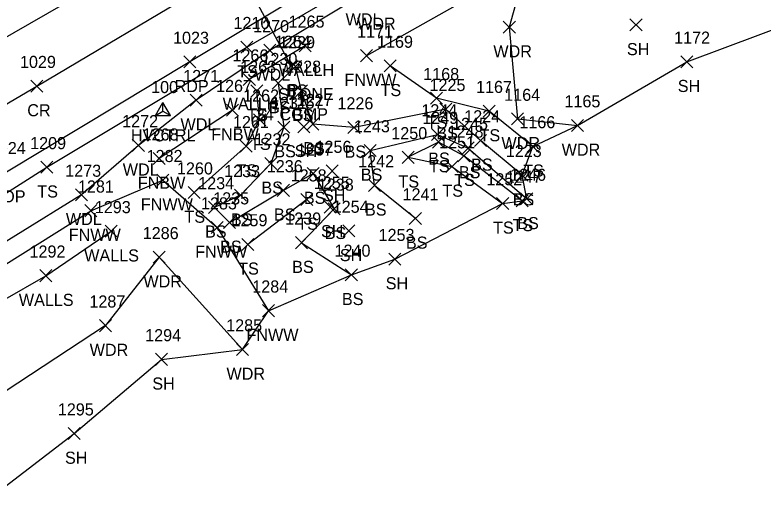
# Model space of a CAD drawing. Extents: x 1526508 to 1531550, y 369926 to 373082.
# Drawn here: x 1530712.1 to 1530836, y 369941.4 to 370020.6 of the extents above; entities that cross this region are included whole.
import ezdxf

# ---------------------------------------------------------------- set-up
doc = ezdxf.new("R2010")
doc.units = 0
for name, color, linetype in [('C_A', 7, 'Continuous'), ('C_I', 7, 'Continuous'), ('CPSM', 7, 'Continuous'), ('D_A', 7, 'Continuous'), ('D_C', 7, 'Continuous'), ('D_I', 7, 'Continuous'), ('D_TIC', 7, 'Continuous'), ('DCP', 7, 'Continuous'), ('DHW', 7, 'Continuous'), ('L_A', 7, 'Continuous'), ('L_I', 7, 'Continuous'), ('L_TIC', 7, 'Continuous'), ('LAWA', 7, 'Continuous'), ('LELB', 7, 'Continuous'), ('LFNC', 7, 'Continuous'), ('LSOGP', 7, 'Continuous'), ('LWS', 7, 'Continuous'), ('P_A', 7, 'Continuous'), ('P_I', 7, 'Continuous'), ('P_TIC', 7, 'Continuous'), ('PET', 7, 'Continuous'), ('PRC', 7, 'Continuous')]:
    doc.layers.add(name, color=color, linetype=linetype)

msp = doc.modelspace()

# ---------------------------------------------------------------- linework, layer by layer
at = {"layer": 'CPSM'}
for p, q in [((1530735.4, 370003.91), (1530736.65, 370006.08)), ((1530737.9, 370003.91), (1530736.65, 370006.08)), ((1530736.65, 370004.63), (1530736.65, 370006.08)), ((1530735.4, 370003.91), (1530736.65, 370004.63)), ((1530736.65, 370004.63), (1530736.65, 370004.63)), ((1530736.65, 370004.63), (1530737.9, 370003.91)), ((1530735.4, 370003.91), (1530737.9, 370003.91))]:
    msp.add_line(p, q, dxfattribs=at)
at = {"layer": 'D_TIC'}
for points in [[(1530759.19, 370014.46), (1530761.19, 370016.46)], [(1530761.19, 370014.46), (1530759.19, 370016.46)], [(1530756.89, 370011.13), (1530758.89, 370013.13)], [(1530758.89, 370011.13), (1530756.89, 370013.13)], [(1530749.95, 370008.87), (1530751.95, 370010.87)], [(1530751.95, 370008.87), (1530749.95, 370010.87)]]:
    msp.add_lwpolyline(points, dxfattribs=at)
at = {"layer": 'DCP'}
msp.add_lwpolyline([(1530757.89, 370012.13), (1530742.1, 370041.37)], dxfattribs=at)
at = {"layer": 'DHW'}
msp.add_lwpolyline([(1530760.19, 370015.46), (1530750.95, 370009.87)], dxfattribs=at)
at = {"layer": 'L_TIC'}
for points in [[(1530792.99, 370017.54), (1530794.99, 370019.54)], [(1530794.99, 370017.54), (1530792.99, 370019.54)], [(1530813.97, 370017.91), (1530815.97, 370019.91)], [(1530815.97, 370017.91), (1530813.97, 370019.91)], [(1530749.55, 370014.24), (1530751.55, 370016.24)], [(1530751.55, 370014.24), (1530749.55, 370016.24)], [(1530753.36, 370013.7), (1530755.36, 370015.7)], [(1530755.36, 370013.7), (1530753.36, 370015.7)], [(1530769.35, 370012.82), (1530771.35, 370014.82)], [(1530771.35, 370012.82), (1530769.35, 370014.82)], [(1530757.58, 370011.05), (1530759.58, 370013.05)], [(1530759.58, 370011.05), (1530757.58, 370013.05)], [(1530773.27, 370011.13), (1530775.27, 370013.13)], [(1530775.27, 370011.13), (1530773.27, 370013.13)], [(1530822.4, 370011.81), (1530824.4, 370013.81)], [(1530824.4, 370011.81), (1530822.4, 370013.81)], [(1530754.73, 370008.28), (1530756.73, 370010.28)], [(1530756.73, 370008.28), (1530754.73, 370010.28)], [(1530751.18, 370006.98), (1530753.18, 370008.98)], [(1530753.18, 370006.98), (1530751.18, 370008.98)], [(1530758.58, 370006.99), (1530760.58, 370008.99)], [(1530760.58, 370006.99), (1530758.58, 370008.99)], [(1530780.92, 370005.79), (1530782.92, 370007.79)], [(1530782.92, 370005.79), (1530780.92, 370007.79)], [(1530741.13, 370005.46), (1530743.13, 370007.46)], [(1530743.13, 370005.46), (1530741.13, 370007.46)], [(1530747.18, 370003.82), (1530749.18, 370005.82)], [(1530749.18, 370003.82), (1530747.18, 370005.82)], [(1530782.47, 370003.97), (1530784.47, 370005.97)], [(1530784.47, 370003.97), (1530782.47, 370005.97)], [(1530789.65, 370003.65), (1530791.65, 370005.65)], [(1530791.65, 370003.65), (1530789.65, 370005.65)], [(1530751.66, 370002.22), (1530753.66, 370004.22)], [(1530753.66, 370002.22), (1530751.66, 370004.22)], [(1530794.33, 370002.35), (1530796.33, 370004.35)], [(1530796.33, 370002.35), (1530794.33, 370004.35)], [(1530755.65, 370001), (1530757.65, 370003)], [(1530757.65, 370001), (1530755.65, 370003)], [(1530758.98, 370001.05), (1530760.98, 370003.05)], [(1530760.98, 370001.05), (1530758.98, 370003.05)], [(1530760.45, 370001.51), (1530762.45, 370003.51)], [(1530762.45, 370001.51), (1530760.45, 370003.51)], [(1530767.28, 370000.94), (1530769.28, 370002.94)], [(1530769.28, 370000.94), (1530767.28, 370002.94)], [(1530804.3, 370001.27), (1530806.3, 370003.27)], [(1530806.3, 370001.27), (1530804.3, 370003.27)], [(1530781.12, 369999.79), (1530783.12, 370001.79)], [(1530783.12, 369999.79), (1530781.12, 370001.79)], [(1530781.29, 369998.53), (1530783.29, 370000.53)], [(1530783.29, 369998.53), (1530781.29, 370000.53)], [(1530788.22, 369998.79), (1530790.22, 370000.79)], [(1530790.22, 369998.79), (1530788.22, 370000.79)], [(1530731.58, 369997.98), (1530733.58, 369999.98)], [(1530733.58, 369997.98), (1530731.58, 369999.98)], [(1530749.41, 369997.84), (1530751.41, 369999.84)], [(1530751.41, 369997.84), (1530749.41, 369999.84)], [(1530769.97, 369997.14), (1530771.97, 369999.14)], [(1530771.97, 369997.14), (1530769.97, 369999.14)], [(1530786.2, 369997.54), (1530788.2, 369999.54)], [(1530788.2, 369997.54), (1530786.2, 369999.54)], [(1530796.88, 369997.81), (1530798.88, 369999.81)], [(1530798.88, 369997.81), (1530796.88, 369999.81)], [(1530735.02, 369995.79), (1530737.02, 369997.79)], [(1530737.02, 369995.79), (1530735.02, 369997.79)], [(1530776.23, 369996), (1530778.23, 369998)], [(1530778.23, 369996), (1530776.23, 369998)], [(1530785.46, 369996.26), (1530787.46, 369998.26)], [(1530787.46, 369996.26), (1530785.46, 369998.26)], [(1530753.5, 369994.98), (1530755.5, 369996.98)], [(1530755.5, 369994.98), (1530753.5, 369996.98)], [(1530716.44, 369994.35), (1530718.44, 369996.35)], [(1530718.44, 369994.35), (1530716.44, 369996.35)], [(1530760.54, 369993.3), (1530762.54, 369995.3)], [(1530762.54, 369993.3), (1530760.54, 369995.3)], [(1530763.65, 369993.73), (1530765.65, 369995.73)], [(1530765.65, 369993.73), (1530763.65, 369995.73)], [(1530783.5, 369994.48), (1530785.5, 369996.48)], [(1530785.5, 369994.48), (1530783.5, 369996.48)], [(1530735.65, 369992.22), (1530737.65, 369994.22)], [(1530737.65, 369992.22), (1530735.65, 369994.22)], [(1530795.1, 369993.05), (1530797.1, 369995.05)], [(1530797.1, 369993.05), (1530795.1, 369995.05)], [(1530770.66, 369991.36), (1530772.66, 369993.36)], [(1530772.66, 369991.36), (1530770.66, 369993.36)], [(1530722.17, 369989.78), (1530724.17, 369991.78)], [(1530724.17, 369989.78), (1530722.17, 369991.78)], [(1530740.8, 369990.17), (1530742.8, 369992.17)], [(1530742.8, 369990.17), (1530740.8, 369992.17)], [(1530748.47, 369989.72), (1530750.47, 369991.72)], [(1530750.47, 369989.72), (1530748.47, 369991.72)], [(1530755.58, 369990.53), (1530757.58, 369992.53)], [(1530757.58, 369990.53), (1530755.58, 369992.53)], [(1530759.49, 369989.01), (1530761.49, 369991.01)], [(1530761.49, 369989.01), (1530759.49, 369991.01)], [(1530791.89, 369988.37), (1530793.89, 369990.37)], [(1530793.89, 369988.37), (1530791.89, 369990.37)], [(1530795.12, 369988.78), (1530797.12, 369990.78)], [(1530797.12, 369988.78), (1530795.12, 369990.78)], [(1530795.87, 369989.11), (1530797.87, 369991.11)], [(1530797.87, 369989.11), (1530795.87, 369991.11)], [(1530723.71, 369987.17), (1530725.71, 369989.17)], [(1530725.71, 369987.17), (1530723.71, 369989.17)], [(1530744.18, 369987.72), (1530746.18, 369989.72)], [(1530746.18, 369987.72), (1530744.18, 369989.72)], [(1530763.33, 369987.78), (1530765.33, 369989.78)], [(1530765.33, 369987.78), (1530763.33, 369989.78)], [(1530763.98, 369987.48), (1530765.98, 369989.48)], [(1530765.98, 369987.48), (1530763.98, 369989.48)], [(1530777.44, 369985.88), (1530779.44, 369987.88)], [(1530779.44, 369985.88), (1530777.44, 369987.88)], [(1530746.66, 369985.21), (1530748.66, 369987.21)], [(1530748.66, 369985.21), (1530746.66, 369987.21)], [(1530727.07, 369983.76), (1530729.07, 369985.76)], [(1530729.07, 369983.76), (1530727.07, 369985.76)], [(1530744.64, 369984.38), (1530746.64, 369986.38)], [(1530746.64, 369984.38), (1530744.64, 369986.38)], [(1530766.44, 369983.82), (1530768.44, 369985.82)], [(1530768.44, 369983.82), (1530766.44, 369985.82)], [(1530749.71, 369981.59), (1530751.71, 369983.59)], [(1530751.71, 369981.59), (1530749.71, 369983.59)], [(1530758.6, 369981.87), (1530760.6, 369983.87)], [(1530760.6, 369981.87), (1530758.6, 369983.87)], [(1530735.04, 369979.46), (1530737.04, 369981.46)], [(1530737.04, 369979.46), (1530735.04, 369981.46)], [(1530774.04, 369979.16), (1530776.04, 369981.16)], [(1530776.04, 369979.16), (1530774.04, 369981.16)], [(1530716.25, 369976.41), (1530718.25, 369978.41)], [(1530718.25, 369976.41), (1530716.25, 369978.41)], [(1530766.84, 369976.55), (1530768.84, 369978.55)], [(1530768.84, 369976.55), (1530766.84, 369978.55)], [(1530753.13, 369970.62), (1530755.13, 369972.62)], [(1530755.13, 369970.62), (1530753.13, 369972.62)], [(1530726.16, 369968.14), (1530728.16, 369970.14)], [(1530728.16, 369968.14), (1530726.16, 369970.14)], [(1530748.81, 369964.19), (1530750.81, 369966.19)], [(1530750.81, 369964.19), (1530748.81, 369966.19)], [(1530735.4, 369962.56), (1530737.4, 369964.56)], [(1530737.4, 369962.56), (1530735.4, 369964.56)], [(1530720.94, 369950.28), (1530722.94, 369952.28)], [(1530722.94, 369950.28), (1530720.94, 369952.28)]]:
    msp.add_lwpolyline(points, dxfattribs=at)
at = {"layer": 'LAWA'}
for points in [[(1530771.43, 370023.13), (1530783.61, 370029.16), (1530797.41, 370030.87), (1530793.99, 370018.54), (1530795.33, 370003.35), (1530805.3, 370002.27)], [(1530769.48, 370023.84), (1530754.36, 370014.7), (1530742.13, 370006.46), (1530732.58, 369998.98), (1530723.17, 369990.78), (1530701.39, 369977.34), (1530688.96, 369968.61), (1530674.75, 369962.19)], [(1530749.81, 369965.19), (1530736.04, 369980.46), (1530727.16, 369969.14), (1530706.46, 369955.58), (1530683.63, 369948.04)]]:
    msp.add_lwpolyline(points, dxfattribs=at)
at = {"layer": 'LELB'}
for points in [[(1530685.88, 369975.28), (1530717.44, 369995.35), (1530750.55, 370015.24), (1530789.81, 370037.94), (1530822.42, 370057.69), (1530849.78, 370074.39), (1530878.97, 370089.95), (1530906.44, 370104.85), (1530934.55, 370113.45), (1530953.41, 370116.76)], [(1530796.1, 369994.05), (1530789.22, 369999.79), (1530783.47, 370004.97), (1530768.28, 370001.94), (1530761.45, 370002.51), (1530759.58, 370007.99), (1530758.58, 370012.05), (1530755.73, 370009.28), (1530756.65, 370002), (1530754.5, 369995.98), (1530749.47, 369990.72), (1530745.18, 369988.72), (1530747.66, 369986.21), (1530756.58, 369991.53), (1530761.54, 369994.3), (1530764.98, 369988.48), (1530759.6, 369982.87), (1530767.84, 369977.55)], [(1530797.88, 369998.81), (1530790.65, 370004.65), (1530781.92, 370006.79), (1530774.27, 370012.13)], [(1530741.8, 369991.17), (1530750.41, 369998.84), (1530752.66, 370003.22), (1530752.18, 370007.98)], [(1530778.44, 369986.88), (1530771.66, 369992.36), (1530770.97, 369998.14), (1530782.12, 370000.79), (1530787.2, 369998.54), (1530796.87, 369990.11)], [(1530796.12, 369989.78), (1530786.46, 369997.26), (1530782.29, 369999.53), (1530777.23, 369997), (1530784.5, 369995.48), (1530792.89, 369989.37)], [(1530760.49, 369990.01), (1530750.71, 369982.59)]]:
    msp.add_lwpolyline(points, dxfattribs=at)
at = {"layer": 'LFNC'}
for points in [[(1530793.41, 370026.8), (1530770.35, 370013.82)], [(1530748.18, 370004.82), (1530736.02, 369996.79)], [(1530676.49, 369959.78), (1530696.26, 369970.98), (1530704.49, 369975.52), (1530724.71, 369988.17), (1530736.65, 369993.22), (1530745.64, 369985.38), (1530754.13, 369971.62)]]:
    msp.add_lwpolyline(points, dxfattribs=at)
at = {"layer": 'LSOGP'}
msp.add_lwpolyline([(1530709.06, 369941.44), (1530721.94, 369951.28), (1530736.4, 369963.56), (1530749.81, 369965.19), (1530754.13, 369971.62), (1530767.84, 369977.55), (1530775.04, 369980.16), (1530792.89, 369989.37), (1530796.12, 369989.78), (1530796.87, 369990.11), (1530796.1, 369994.05), (1530797.88, 369998.81), (1530805.3, 370002.27), (1530823.4, 370012.81), (1530854.24, 370024.39)], dxfattribs=at)
at = {"layer": 'LWS'}
msp.add_lwpolyline([(1530679.21, 369956.07), (1530702.98, 369969.21), (1530717.25, 369977.41), (1530728.07, 369984.76)], dxfattribs=at)
at = {"layer": 'P_TIC'}
for points in [[(1530740.1, 370011.79), (1530742.1, 370013.79)], [(1530742.1, 370011.79), (1530740.1, 370013.79)], [(1530714.76, 370007.79), (1530716.76, 370009.79)], [(1530716.76, 370007.79), (1530714.76, 370009.79)]]:
    msp.add_lwpolyline(points, dxfattribs=at)
at = {"layer": 'PET'}
for points in [[(1530659.86, 369987.59), (1530689.68, 370004.88), (1530725.77, 370025.63), (1530760.95, 370046.59), (1530789.35, 370063.64), (1530821.52, 370083.59), (1530847.47, 370098.66), (1530877.57, 370115.25), (1530907.84, 370128.26), (1530938.81, 370136.76), (1530967.77, 370140.97), (1531005.44, 370146.08), (1531034.99, 370150.93)], [(1531038.44, 370130.38), (1531006.6, 370125.67), (1530965.47, 370120.56), (1530935.63, 370115.81), (1530906.91, 370106.24), (1530877.46, 370092.89), (1530855.5, 370080.74), (1530824.98, 370062.43), (1530800.48, 370048.15), (1530769.96, 370030.14), (1530741.1, 370012.79), (1530710.76, 369994.53), (1530684.03, 369978.66), (1530669.6, 369970.09)]]:
    msp.add_lwpolyline(points, dxfattribs=at)
at = {"layer": 'PRC'}
msp.add_lwpolyline([(1530664.43, 369978.53), (1530688.65, 369992.9), (1530715.76, 370008.79), (1530744.4, 370025.81), (1530774.39, 370044.32), (1530799.13, 370059.29), (1530828.47, 370076.59), (1530863.72, 370096.73), (1530899.64, 370113.89), (1530935.78, 370125.96), (1530974.77, 370132.27), (1531009.67, 370136.56), (1531036.22, 370140.48)], dxfattribs=at)

# ---------------------------------------------------------------- texts
at = {"layer": 'C_A'}
msp.add_text('HVCTRL', height=2, dxfattribs=at).set_placement((1530731.34, 369999.63))
at = {"layer": 'C_I'}
msp.add_text('100', height=2, dxfattribs=at).set_placement((1530734.69, 370007.63))
at = {"layer": 'D_A'}
for s, p in [('WALLH', (1530755.78, 370010.46)), ('P', (1530757.27, 370007.13)), ('WALLH', (1530746.54, 370004.87))]:
    msp.add_text(s, height=2, dxfattribs=at).set_placement(p)
at = {"layer": 'D_C'}
for s, p in [('STONE', (1530755.73, 370006.46)), ('24"CGMP', (1530752.02, 370003.13))]:
    msp.add_text(s, height=2, dxfattribs=at).set_placement(p)
at = {"layer": 'D_I'}
for s, p in [('1265', (1530757.45, 370018.46)), ('1264', (1530755.15, 370015.13)), ('1266', (1530748.15, 370012.87))]:
    msp.add_text(s, height=2, dxfattribs=at).set_placement(p)
at = {"layer": 'L_A'}
for s, p in [('WDL', (1530766.89, 370018.84)), ('WDR', (1530768.79, 370018.13)), ('WDR', (1530791.35, 370013.54)), ('SH', (1530813.46, 370013.91)), ('TS', (1530748.96, 370010.24)), ('WDL', (1530751.78, 370009.7)), ('FNWW', (1530766.7, 370008.82)), ('BS', (1530757.02, 370007.05)), ('TS', (1530772.68, 370007.13)), ('SH', (1530821.88, 370007.81)), ('BS', (1530754.18, 370004.28)), ('TS', (1530750.59, 370002.98)), ('BS', (1530758.02, 370002.99)), ('WDL', (1530739.55, 370001.46)), ('TS', (1530780.32, 370001.79)), ('FNBW', (1530744.65, 369999.82)), ('BS', (1530781.91, 369999.97)), ('TS', (1530789.06, 369999.65)), ('TS', (1530751.07, 369998.22)), ('WDR', (1530792.69, 369998.35)), ('BS', (1530755.09, 369997)), ('SH', (1530758.47, 369997.05)), ('BS', (1530759.89, 369997.51)), ('BS', (1530766.72, 369996.94)), ('WDR', (1530802.66, 369997.27)), ('BS', (1530780.57, 369995.79)), ('TS', (1530780.7, 369994.53)), ('BS', (1530787.66, 369994.79)), ('WDL', (1530730, 369993.98)), ('TS', (1530748.82, 369993.84)), ('BS', (1530785.64, 369993.54)), ('TS', (1530796.29, 369993.81)), ('BS', (1530769.41, 369993.14)), ('TS', (1530775.64, 369992)), ('TS', (1530784.87, 369992.26)), ('FNBW', (1530732.49, 369991.79)), ('BS', (1530752.95, 369990.98)), ('TS', (1530715.85, 369990.35)), ('SH', (1530763.14, 369989.73)), ('TS', (1530782.91, 369990.48)), ('BS', (1530759.98, 369989.3)), ('BS', (1530794.55, 369989.05)), ('FNWW', (1530732.99, 369988.22)), ('BS', (1530770.1, 369987.36)), ('TS', (1530740.21, 369986.17)), ('BS', (1530755.03, 369986.53)), ('WDL', (1530720.58, 369985.78)), ('BS', (1530747.91, 369985.72)), ('TS', (1530758.9, 369985.01)), ('TS', (1530794.53, 369984.78)), ('BS', (1530795.31, 369985.11)), ('BS', (1530743.62, 369983.72)), ('SH', (1530762.82, 369983.78)), ('BS', (1530763.42, 369983.48)), ('TS', (1530791.3, 369984.37)), ('FNWW', (1530721.05, 369983.17)), ('BS', (1530746.11, 369981.21)), ('BS', (1530776.88, 369981.88)), ('WALLS', (1530723.61, 369979.76)), ('FNWW', (1530741.99, 369980.38)), ('SH', (1530765.93, 369979.82)), ('TS', (1530749.11, 369977.59)), ('BS', (1530758.04, 369977.87)), ('WDR', (1530733.41, 369975.46)), ('SH', (1530773.53, 369975.16)), ('WALLS', (1530712.79, 369972.41)), ('BS', (1530766.28, 369972.55)), ('FNWW', (1530750.48, 369966.62)), ('WDR', (1530724.52, 369964.14)), ('WDR', (1530747.17, 369960.19)), ('SH', (1530734.89, 369958.56)), ('SH', (1530720.43, 369946.28))]:
    msp.add_text(s, height=2, dxfattribs=at).set_placement(p)
at = {"layer": 'L_I'}
for s, p in [('1210', (1530748.33, 370018.24)), ('1270', (1530751.58, 370017.7)), ('1171', (1530768.79, 370016.82)), ('1172', (1530821.27, 370015.81)), ('1229', (1530755.88, 370015.05)), ('1169', (1530772.09, 370015.13)), ('1230', (1530752.96, 370012.28)), ('1263', (1530749.44, 370010.98)), ('1228', (1530756.89, 370010.99)), ('1271', (1530740, 370009.46)), ('1168', (1530779.74, 370009.79)), ('1267', (1530745.44, 370007.82)), ('1225', (1530780.78, 370007.97)), ('1167', (1530788.48, 370007.65)), ('1262', (1530749.92, 370006.22)), ('1164', (1530793.15, 370006.35)), ('1231', (1530754.53, 370005)), ('1257', (1530757.29, 370005.05)), ('1227', (1530758.76, 370005.51)), ('1226', (1530765.53, 370004.94)), ('1165', (1530803.12, 370005.27)), ('1244', (1530779.43, 370003.79)), ('1272', (1530729.89, 370001.98)), ('1249', (1530779.59, 370002.53)), ('1224', (1530786.53, 370002.79)), ('1261', (1530748.24, 370001.84)), ('1243', (1530768.27, 370001.14)), ('1245', (1530784.51, 370001.54)), ('1166', (1530795.65, 370001.81)), ('1268', (1530733.28, 369999.79)), ('1250', (1530774.45, 370000)), ('1248', (1530783.77, 370000.26)), ('1209', (1530714.66, 369998.35)), ('1232', (1530751.81, 369998.98)), ('1251', (1530782.37, 369998.48)), ('1237', (1530758.84, 369997.3)), ('1256', (1530761.91, 369997.73)), ('1223', (1530793.41, 369997.05)), ('1282', (1530733.95, 369996.22)), ('1236', (1530753.84, 369994.53)), ('1242', (1530768.97, 369995.36)), ('1273', (1530720.47, 369993.78)), ('1260', (1530738.97, 369994.17)), ('1233', (1530746.78, 369993.72)), ('1258', (1530757.8, 369993.01)), ('1252', (1530790.19, 369992.37)), ('1247', (1530793.43, 369992.78)), ('1246', (1530794.12, 369993.11)), ('1281', (1530722.58, 369991.17)), ('1234', (1530742.49, 369991.72)), ('1255', (1530761.63, 369991.78)), ('1238', (1530762.29, 369991.48)), ('1241', (1530776.32, 369989.88)), ('1283', (1530742.95, 369988.38)), ('1235', (1530744.97, 369989.21)), ('1293', (1530725.37, 369987.76)), ('1254', (1530764.75, 369987.82)), ('1239', (1530756.9, 369985.87)), ('1259', (1530748, 369985.59)), ('1286', (1530733.3, 369983.46)), ('1253', (1530772.35, 369983.16)), ('1292', (1530714.56, 369980.41)), ('1240', (1530765.06, 369980.55)), ('1284', (1530751.44, 369974.62)), ('1287', (1530724.47, 369972.14)), ('1285', (1530747.12, 369968.19)), ('1294', (1530733.71, 369966.56)), ('1295', (1530719.25, 369954.28))]:
    msp.add_text(s, height=2, dxfattribs=at).set_placement(p)
at = {"layer": 'P_A'}
for s, p in [('RDP', (1530738.58, 370007.79)), ('CR', (1530714.19, 370003.79)), ('RDP', (1530708.25, 369989.53))]:
    msp.add_text(s, height=2, dxfattribs=at).set_placement(p)
at = {"layer": 'P_I'}
for s, p in [('1023', (1530738.32, 370015.79)), ('1029', (1530712.98, 370011.79)), ('1024', (1530707.99, 369997.53))]:
    msp.add_text(s, height=2, dxfattribs=at).set_placement(p)

doc.saveas('drawing.dxf')
